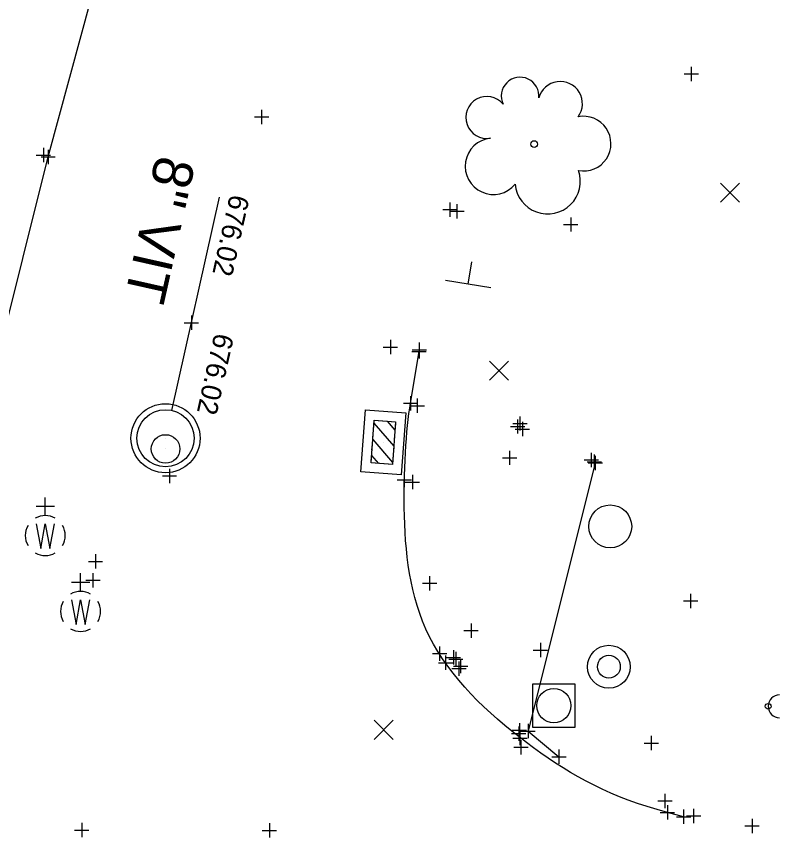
# Model space of a CAD drawing. Extents: x 2188719 to 2189819, y 654569 to 659504.
# Drawn here: x 2189170.1 to 2189223.6, y 655623.5 to 655681 of the extents above; entities that cross this region are included whole.
import ezdxf

# ---------------------------------------------------------------- set-up
doc = ezdxf.new("R2010")
doc.units = 0
for name, color, linetype in [('DR_X_Cells', 7, 'Continuous'), ('DR_X_Elev_Flow', 7, 'Continuous'), ('DR_X_Storm_Sewer', 7, 'Continuous'), ('DR_X_Text', 7, 'Continuous'), ('GK_Drainage_Nodes', 7, 'Continuous'), ('PV_X_Curb', 7, 'Continuous'), ('PV_X_EOP', 7, 'Continuous'), ('SC_Scratch1', 7, 'Continuous'), ('SG_X_Poles', 7, 'Continuous'), ('SN_X_Public', 7, 'Continuous'), ('SV_P_Mon_Cells_Set', 7, 'Continuous'), ('SV_X_Mon_Cells_Found', 7, 'Continuous'), ('SV_X_Random_Point', 7, 'Continuous'), ('SV_X_Shot_Marker', 7, 'Continuous'), ('UT_X_Misc_Cells', 7, 'Continuous'), ('UT_X_Water_Cells', 7, 'Continuous'), ('VG_X_Cells', 7, 'Continuous')]:
    doc.layers.add(name, color=color, linetype=linetype)

msp = doc.modelspace()

# ---------------------------------------------------------------- linework, layer by layer
at = {"layer": 'DR_X_Cells'}
for p, q in [((2189195.142, 655652.237), (2189195.18, 655652.748)), ((2189195.164, 655652.531), (2189196.549, 655650.925)), ((2189195.18, 655652.748), (2189195.741, 655652.706)), ((2189196.092, 655652.68), (2189196.633, 655652.053)), ((2189196.115, 655652.679), (2189196.676, 655652.637)), ((2189196.676, 655652.637), (2189196.638, 655652.126)), ((2189195.083, 655651.439), (2189195.114, 655651.863)), ((2189195.08, 655651.403), (2189196.465, 655649.796)), ((2189196.61, 655651.752), (2189196.579, 655651.328)), ((2189195.024, 655650.641), (2189195.055, 655651.065)), ((2189196.549, 655650.925), (2189196.52, 655650.53)), ((2189194.958, 655649.756), (2189194.996, 655650.267)), ((2189194.997, 655650.275), (2189195.477, 655649.718)), ((2189196.492, 655650.156), (2189196.454, 655649.645)), ((2189195.519, 655649.715), (2189194.958, 655649.756)), ((2189196.454, 655649.645), (2189195.893, 655649.687))]:
    msp.add_line(p, q, dxfattribs=at)
for points in [[(2189197.39, 655653.253), (2189197.07, 655648.931), (2189194.244, 655649.141), (2189194.564, 655653.462)], [(2189196.676, 655652.637), (2189196.454, 655649.645), (2189194.958, 655649.756), (2189195.18, 655652.748)], [(2189196.676, 655652.637), (2189196.454, 655649.645), (2189194.958, 655649.756), (2189195.18, 655652.748)]]:
    msp.add_lwpolyline(points, close=True, dxfattribs=at)
for centre, radius in [((2189180.569, 655651.48), 2.417), ((2189180.569, 655651.48), 2), ((2189180.569, 655650.73), 1)]:
    msp.add_circle(centre, radius, dxfattribs=at)
at = {"layer": 'DR_X_Elev_Flow'}
for p, q in [((2189182.379, 655660.061), (2189182.379, 655659.061)), ((2189181.879, 655659.561), (2189182.879, 655659.561)), ((2189182.379, 655659.561), (2189182.379, 655659.561))]:
    msp.add_line(p, q, dxfattribs=at)
at = {"layer": 'DR_X_Storm_Sewer'}
msp.add_line((2189181.006, 655653.432), (2189184.35, 655668.362), dxfattribs=at)
at = {"layer": 'GK_Drainage_Nodes'}
for p, q in [((2189180.569, 655653.48), (2189180.569, 655653.48)), ((2189195.928, 655652.693), (2189195.928, 655652.693)), ((2189180.569, 655651.48), (2189180.569, 655651.48)), ((2189180.569, 655651.48), (2189180.569, 655651.48)), ((2189194.404, 655651.301), (2189194.404, 655651.301)), ((2189195.069, 655651.252), (2189195.069, 655651.252)), ((2189195.817, 655651.197), (2189195.817, 655651.197)), ((2189180.569, 655650.73), (2189180.569, 655650.73)), ((2189196.565, 655651.141), (2189196.565, 655651.141)), ((2189196.565, 655651.141), (2189196.565, 655651.141)), ((2189196.565, 655651.141), (2189196.565, 655651.141)), ((2189197.23, 655651.092), (2189197.23, 655651.092)), ((2189180.569, 655649.48), (2189180.569, 655649.48)), ((2189195.706, 655649.701), (2189195.706, 655649.701))]:
    msp.add_line(p, q, dxfattribs=at)
msp.add_circle((2189180.569, 655651.48), 2, dxfattribs=at)
at = {"layer": 'PV_X_Curb'}
for p, q in [((2189210.654, 655649.755), (2189205.947, 655630.986)), ((2189205.947, 655630.986), (2189208.112, 655629.196))]:
    msp.add_line(p, q, dxfattribs=at)
at = {"layer": 'PV_X_EOP'}
for p, q in [((2189172.353, 655671.172), (2189178.828, 655695.081)), ((2189162.595, 655632.13), (2189172.353, 655671.172)), ((2189197.722, 655653.935), (2189198.321, 655657.563)), ((2189216.836, 655624.994), (2189215.701, 655625.293))]:
    msp.add_line(p, q, dxfattribs=at)
msp.add_open_spline([(2189215.701, 655625.293), (2189211.783, 655626.325), (2189206.345, 655629.324), (2189198.16, 655636.745), (2189196.992, 655646.1), (2189197.424, 655652.132), (2189197.722, 655653.935)], degree=3, dxfattribs=at)
at = {"layer": 'SG_X_Poles'}
msp.add_lwpolyline([(2189206.255, 655631.271), (2189209.255, 655631.271), (2189209.255, 655634.271), (2189206.255, 655634.271)], close=True, dxfattribs=at)
msp.add_circle((2189207.755, 655632.771), 1.2, dxfattribs=at)
at = {"layer": 'SN_X_Public'}
for p, q in [((2189201.758, 655662.261), (2189202.02, 655663.839)), ((2189203.336, 655661.999), (2189200.18, 655662.523))]:
    msp.add_line(p, q, dxfattribs=at)
at = {"layer": 'SV_P_Mon_Cells_Set'}
msp.add_circle((2189211.703, 655645.315), 1.5, dxfattribs=at)
at = {"layer": 'SV_X_Mon_Cells_Found'}
for radius in [1.5, 0.8]:
    msp.add_circle((2189211.607, 655635.493), radius, dxfattribs=at)
at = {"layer": 'SV_X_Random_Point'}
for p, q in [((2189219.429, 655668.002), (2189220.763, 655669.337)), ((2189219.429, 655669.337), (2189220.763, 655668.002)), ((2189203.254, 655655.541), (2189204.588, 655656.876)), ((2189203.254, 655656.876), (2189204.588, 655655.541)), ((2189195.177, 655630.409), (2189196.511, 655631.744)), ((2189195.177, 655631.744), (2189196.511, 655630.409))]:
    msp.add_line(p, q, dxfattribs=at)
at = {"layer": 'SV_X_Shot_Marker'}
for p, q in [((2189217.372, 655677.476), (2189217.372, 655676.476)), ((2189216.872, 655676.976), (2189217.872, 655676.976)), ((2189217.372, 655676.976), (2189217.372, 655676.976)), ((2189187.293, 655674.464), (2189187.293, 655673.464)), ((2189186.793, 655673.964), (2189187.793, 655673.964)), ((2189187.293, 655673.964), (2189187.293, 655673.964)), ((2189172.02, 655671.803), (2189172.02, 655670.803)), ((2189172.02, 655671.803), (2189172.02, 655670.803)), ((2189172.353, 655671.672), (2189172.353, 655670.672)), ((2189171.52, 655671.303), (2189172.52, 655671.303)), ((2189171.52, 655671.303), (2189172.52, 655671.303)), ((2189171.853, 655671.172), (2189172.853, 655671.172)), ((2189172.02, 655671.303), (2189172.02, 655671.303)), ((2189172.02, 655671.303), (2189172.02, 655671.303)), ((2189172.353, 655671.172), (2189172.353, 655671.172)), ((2189200.475, 655667.985), (2189200.475, 655666.985)), ((2189200.968, 655667.864), (2189200.968, 655666.864)), ((2189199.975, 655667.485), (2189200.975, 655667.485)), ((2189200.468, 655667.364), (2189201.468, 655667.364)), ((2189200.475, 655667.485), (2189200.475, 655667.485)), ((2189200.968, 655667.364), (2189200.968, 655667.364)), ((2189208.936, 655666.94), (2189208.936, 655665.94)), ((2189208.436, 655666.44), (2189209.436, 655666.44)), ((2189208.936, 655666.44), (2189208.936, 655666.44)), ((2189196.312, 655658.367), (2189196.312, 655657.367)), ((2189198.337, 655658.175), (2189198.337, 655657.175)), ((2189195.812, 655657.867), (2189196.812, 655657.867)), ((2189196.312, 655657.867), (2189196.312, 655657.867)), ((2189197.821, 655657.563), (2189198.821, 655657.563)), ((2189197.837, 655657.675), (2189198.837, 655657.675)), ((2189198.321, 655658.063), (2189198.321, 655657.063)), ((2189198.321, 655657.563), (2189198.321, 655657.563)), ((2189198.337, 655657.675), (2189198.337, 655657.675)), ((2189197.722, 655654.435), (2189197.722, 655653.435)), ((2189198.191, 655654.258), (2189198.191, 655653.258)), ((2189197.222, 655653.935), (2189198.222, 655653.935)), ((2189197.691, 655653.758), (2189198.691, 655653.758)), ((2189197.722, 655653.935), (2189197.722, 655653.935)), ((2189198.191, 655653.758), (2189198.191, 655653.758)), ((2189205.382, 655653.013), (2189205.382, 655652.013)), ((2189204.882, 655652.513), (2189205.882, 655652.513)), ((2189205.213, 655652.803), (2189205.213, 655651.803)), ((2189205.382, 655652.513), (2189205.382, 655652.513)), ((2189205.556, 655652.621), (2189205.556, 655651.621)), ((2189204.713, 655652.303), (2189205.713, 655652.303)), ((2189205.056, 655652.121), (2189206.056, 655652.121)), ((2189205.213, 655652.303), (2189205.213, 655652.303)), ((2189205.556, 655652.121), (2189205.556, 655652.121)), ((2189204.156, 655650.11), (2189205.156, 655650.11)), ((2189204.656, 655650.61), (2189204.656, 655649.61)), ((2189204.656, 655650.11), (2189204.656, 655650.11)), ((2189210.374, 655650.463), (2189210.374, 655649.463)), ((2189210.589, 655650.34), (2189210.589, 655649.34)), ((2189210.654, 655650.255), (2189210.654, 655649.255)), ((2189209.874, 655649.963), (2189210.874, 655649.963)), ((2189210.089, 655649.84), (2189211.089, 655649.84)), ((2189210.154, 655649.755), (2189211.154, 655649.755)), ((2189210.374, 655649.963), (2189210.374, 655649.963)), ((2189210.589, 655649.84), (2189210.589, 655649.84)), ((2189210.654, 655649.755), (2189210.654, 655649.755)), ((2189180.848, 655649.349), (2189180.848, 655648.349)), ((2189197.28, 655649.064), (2189197.28, 655648.064)), ((2189197.858, 655648.917), (2189197.858, 655647.917)), ((2189180.348, 655648.849), (2189181.348, 655648.849)), ((2189180.848, 655648.849), (2189180.848, 655648.849)), ((2189196.78, 655648.564), (2189197.78, 655648.564)), ((2189197.28, 655648.564), (2189197.28, 655648.564)), ((2189197.358, 655648.417), (2189198.358, 655648.417)), ((2189197.858, 655648.417), (2189197.858, 655648.417)), ((2189175.669, 655643.361), (2189175.669, 655642.361)), ((2189175.169, 655642.861), (2189176.169, 655642.861)), ((2189175.669, 655642.861), (2189175.669, 655642.861)), ((2189175.492, 655642.044), (2189175.492, 655641.044)), ((2189174.992, 655641.544), (2189175.992, 655641.544)), ((2189175.492, 655641.544), (2189175.492, 655641.544)), ((2189199.059, 655641.836), (2189199.059, 655640.836)), ((2189198.559, 655641.336), (2189199.559, 655641.336)), ((2189199.059, 655641.336), (2189199.059, 655641.336)), ((2189217.333, 655640.602), (2189217.333, 655639.602)), ((2189216.833, 655640.102), (2189217.833, 655640.102)), ((2189217.333, 655640.102), (2189217.333, 655640.102)), ((2189201.461, 655638.025), (2189202.461, 655638.025)), ((2189201.961, 655638.525), (2189201.961, 655637.525)), ((2189201.961, 655638.025), (2189201.961, 655638.025)), ((2189199.754, 655636.908), (2189199.754, 655635.908)), ((2189206.813, 655637.154), (2189206.813, 655636.154)), ((2189199.254, 655636.408), (2189200.254, 655636.408)), ((2189199.754, 655636.408), (2189199.754, 655636.408)), ((2189200.177, 655636.273), (2189200.177, 655635.273)), ((2189200.727, 655636.64), (2189200.727, 655635.64)), ((2189200.895, 655636.523), (2189200.895, 655635.523)), ((2189206.313, 655636.654), (2189207.313, 655636.654)), ((2189206.813, 655636.654), (2189206.813, 655636.654)), ((2189199.677, 655635.773), (2189200.677, 655635.773)), ((2189200.177, 655635.773), (2189200.177, 655635.773)), ((2189200.227, 655636.14), (2189201.227, 655636.14)), ((2189200.395, 655636.023), (2189201.395, 655636.023)), ((2189200.727, 655636.14), (2189200.727, 655636.14)), ((2189200.895, 655636.023), (2189200.895, 655636.023)), ((2189201.115, 655635.858), (2189201.115, 655634.858)), ((2189201.226, 655636.032), (2189201.226, 655635.032)), ((2189200.615, 655635.358), (2189201.615, 655635.358)), ((2189200.726, 655635.532), (2189201.726, 655635.532)), ((2189201.115, 655635.358), (2189201.115, 655635.358)), ((2189201.226, 655635.532), (2189201.226, 655635.532)), ((2189205.301, 655631.315), (2189205.301, 655630.315)), ((2189205.339, 655631.548), (2189205.339, 655630.548)), ((2189205.947, 655631.486), (2189205.947, 655630.486)), ((2189204.801, 655630.815), (2189205.801, 655630.815)), ((2189204.839, 655631.048), (2189205.839, 655631.048)), ((2189205.301, 655630.815), (2189205.301, 655630.815)), ((2189205.339, 655631.048), (2189205.339, 655631.048)), ((2189205.38, 655630.994), (2189205.38, 655629.994)), ((2189205.447, 655630.986), (2189206.447, 655630.986)), ((2189205.947, 655630.986), (2189205.947, 655630.986)), ((2189214.574, 655630.645), (2189214.574, 655629.645)), ((2189204.88, 655630.494), (2189205.88, 655630.494)), ((2189205.38, 655630.494), (2189205.38, 655630.494)), ((2189205.452, 655630.356), (2189205.452, 655629.356)), ((2189214.074, 655630.145), (2189215.074, 655630.145)), ((2189214.574, 655630.145), (2189214.574, 655630.145)), ((2189204.952, 655629.856), (2189205.952, 655629.856)), ((2189205.452, 655629.856), (2189205.452, 655629.856)), ((2189208.112, 655629.696), (2189208.112, 655628.696)), ((2189207.612, 655629.196), (2189208.612, 655629.196)), ((2189208.112, 655629.196), (2189208.112, 655629.196)), ((2189215.534, 655626.605), (2189215.534, 655625.605)), ((2189215.034, 655626.105), (2189216.034, 655626.105)), ((2189215.534, 655626.105), (2189215.534, 655626.105)), ((2189215.701, 655625.793), (2189215.701, 655624.793)), ((2189216.836, 655625.494), (2189216.836, 655624.494)), ((2189217.538, 655625.546), (2189217.538, 655624.546)), ((2189215.201, 655625.293), (2189216.201, 655625.293)), ((2189215.701, 655625.293), (2189215.701, 655625.293)), ((2189216.336, 655624.994), (2189217.336, 655624.994)), ((2189216.836, 655624.994), (2189216.836, 655624.994)), ((2189217.038, 655625.046), (2189218.038, 655625.046)), ((2189217.538, 655625.046), (2189217.538, 655625.046)), ((2189221.629, 655624.852), (2189221.629, 655623.852)), ((2189174.7, 655624.558), (2189174.7, 655623.558)), ((2189187.839, 655624.536), (2189187.839, 655623.536)), ((2189221.129, 655624.352), (2189222.129, 655624.352)), ((2189221.629, 655624.352), (2189221.629, 655624.352)), ((2189174.2, 655624.058), (2189175.2, 655624.058)), ((2189174.7, 655624.058), (2189174.7, 655624.058)), ((2189187.339, 655624.036), (2189188.339, 655624.036)), ((2189187.839, 655624.036), (2189187.839, 655624.036))]:
    msp.add_line(p, q, dxfattribs=at)
at = {"layer": 'UT_X_Misc_Cells'}
msp.add_circle((2189222.758, 655632.722), 0.2, dxfattribs=at)
msp.add_arc((2189223.558, 655632.722), 0.8, 90, 270, dxfattribs=at)
at = {"layer": 'UT_X_Water_Cells'}
for p, q in [((2189172.155, 655646.07), (2189172.155, 655647.342)), ((2189172.79, 655646.707), (2189171.518, 655646.707)), ((2189172.155, 655644.67), (2189172.155, 655644.67)), ((2189174.626, 655640.762), (2189174.626, 655642.033)), ((2189175.261, 655641.398), (2189173.989, 655641.398)), ((2189174.626, 655639.362), (2189174.626, 655639.362))]:
    msp.add_line(p, q, dxfattribs=at)
for points in [[(2189171.518, 655645.49), (2189171.837, 655643.767), (2189172.155, 655645.49), (2189172.475, 655643.767), (2189172.792, 655645.49)], [(2189173.989, 655640.182), (2189174.308, 655638.458), (2189174.626, 655640.182), (2189174.946, 655638.458), (2189175.263, 655640.182)]]:
    msp.add_lwpolyline(points, dxfattribs=at)
for centre, start, end in [((2189172.155, 655644.671), 60.01836, 120.01574), ((2189172.155, 655644.671), 150.01836, 209.98164), ((2189172.155, 655644.671), 330.01836, 29.98164), ((2189172.155, 655644.671), 239.98426, 299.98164), ((2189174.626, 655639.363), 60.01836, 120.01574), ((2189174.626, 655639.363), 150.01836, 209.98164), ((2189174.626, 655639.363), 330.01836, 29.98164), ((2189174.626, 655639.363), 239.98426, 299.98164)]:
    msp.add_arc(centre, 1.4, start, end, dxfattribs=at)
at = {"layer": 'VG_X_Cells'}
msp.add_circle((2189206.377, 655672.064), 0.24, dxfattribs=at)
for centre, radius, start, end in [((2189205.393, 655675.432), 1.317, 354.0047, 205.97412), ((2189208.203, 655674.894), 1.553, 323.82996, 165.0376), ((2189203.068, 655673.929), 1.471, 39.06254, 279.54124), ((2189209.837, 655672.1), 1.915, 259.14531, 101.45961), ((2189203.524, 655670.516), 1.974, 96.17219, 320.57371), ((2189207.323, 655669.459), 2.284, 184.94757, 19.45715)]:
    msp.add_arc(centre, radius, start, end, dxfattribs=at)

# ---------------------------------------------------------------- texts
at = {"layer": 'DR_X_Text'}
msp.add_text('8" VIT', height=2.8, rotation=257.37483, dxfattribs=at).set_placement((2189179.939, 655671.382))
at = {"layer": 'SC_Scratch1'}
for p in [(2189185.094, 655668.606), (2189184.007, 655658.9)]:
    msp.add_text('676.02', height=1.4, rotation=257.37483, dxfattribs=at).set_placement(p)

doc.saveas('drawing.dxf')
